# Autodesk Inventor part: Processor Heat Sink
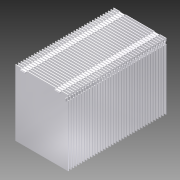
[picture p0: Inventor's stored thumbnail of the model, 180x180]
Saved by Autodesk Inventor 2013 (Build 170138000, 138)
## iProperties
Created: 2005-11
Material: Allgemein
Document SubType Name: Sheet Metal
Mass: 38.8498 g
Surface Area: 1566.91 cm^2
Volume: 38.8498 cm^3
Density: 1 g/cm^3
Sheet Metal Rule: 0.5 mm
Author: Autodesk, Inc.
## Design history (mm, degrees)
node "Face1"
node "Flange1"
node "Flange2"
mirror "Mirror1"
node "Flange3"
sketch "Sketch6"
  geometry: L1 (0, 0)-(0, 50) reference; L2 (40, 0)-(0, 0) reference; L3 (20, 60)-(20, -10) reference; C1 r 1.5 at (10, 5); C2 r 1.5 at (30, 5)
  constraints: 2 centre point, 1 equal radius, 1 symmetric about line
  dimensions: "d31" = 3 diameter of C1; "d32" = 5 distance from line of L2 C1.centre; "d33" = 10 distance from line of L1 C1.centre
extrude "Extrusion1" join sketch "Sketch6" stored distance "d34" = 10; taper "d35" = 0 deg
workplane "Work Plane3"
body "Solid1"
pattern_linear "Rectangular Pattern1" dims "d30" = 2
sketch "Sketch2"
  geometry: L1 (0, -10)-(0, 60) reference; L2 (-28, 0)-(28, 0) reference; L3 (-20, 0)-(20, 0); L4 (20, 0)-(20, 50); L5 (20, 50)-(-20, 50); L6 (-20, 50)-(-20, 0); 1 further point
  constraints: 8 end point, 2 parallel, 1 horizontal, 1 perpendicular, 1 point on line, 1 other
  dimensions: "d0" = 40 distance of L4.end L5.end; "d1" = 50 distance of L5.end L3.start
face "Plate1" dims "Thickness" = 0.5
sketch "Sketch3"
  geometry: L1 (5, 0)-(9, 0); L2 (9, 0)-(9, -2); L3 (9, -2)-(5, -2); L4 (5, -2)-(5, 0)
  constraints: 8 end point
face "Plate2" dims "d3" = 5, "d4" = 4, "d7" = 1 (= MinimumRemnant), "d9" = 2, "d10" = 90 deg, "d11" = 0.2, "SeamGap" = 0.01, "Thickness" = 0.5
bend "Bend1" dims "d5" = 0.5 (= BendReliefWidth), "d6" = 0.25 (= BendReliefDepth), "d7" = 1 (= MinimumRemnant), "d8" = 0.5 (= BendRadius), "d9" = 2, "d10" = 90 deg, "d11" = 0.2, "SeamGap" = 0.01, "Thickness" = 0.5
sketch "Sketch4"
  geometry: L1 through (2, 0) direction (1, 0); L2 (4, 0)-(4, -1); L3 (4, -1)-(0, -1); L4 through (0, -0.5) direction (0, 1)
  constraints: 6 end point, 1 horizontal, 1 perpendicular, 1 vertical
face "Plate3" dims "d14" = 1 (= MinimumRemnant), "d16" = 1, "d17" = 90 deg, "d18" = 0.2, "SeamGap" = 0.01, "Thickness" = 0.5
bend "Bend2" dims "d12" = 0.5 (= BendReliefWidth), "d13" = 0.25 (= BendReliefDepth), "d14" = 1 (= MinimumRemnant), "d15" = 0.5 (= BendRadius), "d16" = 1, "d17" = 90 deg, "d18" = 0.2, "SeamGap" = 0.01, "Thickness" = 0.5
sketch "Sketch5"
  geometry: L1 (0, 48)-(0, 46); L2 (0, 46)-(2, 46); L3 (2, 46)-(2, 48); L4 (2, 48)-(0, 48)
  constraints: 8 end point
face "Plate4" dims "d19" = 2, "d20" = 2, "d23" = 1 (= MinimumRemnant), "d25" = 2, "d26" = 70 deg, "d27" = 0.2, "SeamGap" = 0.01, "Thickness" = 0.5
bend "Bend3" dims "d21" = 0.5 (= BendReliefWidth), "d22" = 0.25 (= BendReliefDepth), "d23" = 1 (= MinimumRemnant), "d24" = 0.5 (= BendRadius), "d25" = 2, "d26" = 70 deg, "d27" = 0.2, "SeamGap" = 0.01, "Thickness" = 0.5
other parameters: "BendRadius" = 0.5 (= Thickness), "BendReliefWidth" = 0.5 (= Thickness), "BendReliefDepth" = 0.25 (= 0.5 x Thickness), "CornerReliefSize" = 2 (= 4 x Thickness), "MinimumRemnant" = 1 (= 2 x Thickness), "TransitionRadius" = 0.5 (= BendRadius), "d2" = 0.5 (= BendRadius), "JacobiRadiusSize" = 0.5 (= Thickness), "GapSize" = 0.5 (= Thickness)
